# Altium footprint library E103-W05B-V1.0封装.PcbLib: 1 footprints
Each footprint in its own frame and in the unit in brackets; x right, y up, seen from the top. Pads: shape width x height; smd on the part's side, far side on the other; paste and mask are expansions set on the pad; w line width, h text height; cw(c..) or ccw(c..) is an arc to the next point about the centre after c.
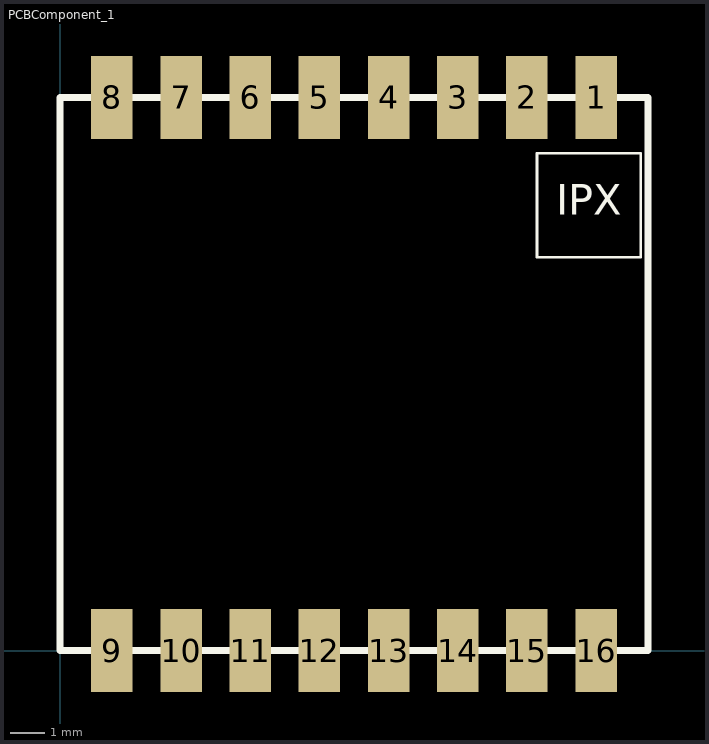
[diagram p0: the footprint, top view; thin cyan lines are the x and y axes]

## PCBComponent_1 [mm]
pads (16):
  rect 1.2x2.4 smd: 1(15.5,16) 2(13.5,16) 3(11.5,16) 4(9.5,16) 5(7.5,16) 6(5.5,16) 7(3.5,16) 8(1.5,16) 9(1.5,0) 10(3.5,0) 11(5.5,0) 12(7.5,0) 13(9.5,0) 14(11.5,0) 15(13.5,0) 16(15.5,0)
Top Overlay:
  lines w0.076: 13.79,11.38 16.79,11.38 16.79,14.38 13.79,14.38 13.79,11.38
  lines w0.2: 0,0 17,0 17,16 0,16 0,0
  text "IPX" at 14.351,12.319 h1.5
